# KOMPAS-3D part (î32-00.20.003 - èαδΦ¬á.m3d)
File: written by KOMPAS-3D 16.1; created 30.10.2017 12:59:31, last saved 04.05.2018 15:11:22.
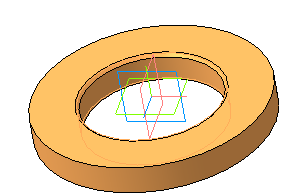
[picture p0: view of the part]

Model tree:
1. Эскиз:12
2. Операция вращения:1
     Угол 1 = 360
3. Условное изображение резьбы:1  (labels: M125x3)
     Длина резьбы = 25; Шаг резьбы = 3; Номинальный диаметр резьбы = 125
4. Подгонка:1
5. Фаска:2
     Угол = 45; Длина 1 = 1; Длина 2 = 1
6. Эскиз:14
7. Вырезать элемент выдавливания:1
     Толщина стенки 2 = 4; Расстояние 2 = 5; Расстояние 1 = 10.5; На расстояние 1 = 14.5
8. Фаска:3
     Угол = 45; Длина 1 = 3; Длина 2 = 3
9. Фаска:4
     Угол = 45; Длина 1 = 3; Длина 2 = 3
10. Эскиз:15
11. Вырезать элемент выдавливания:2
     Расстояние 1 = 5
12. Эскиз:16
13. Эскиз:13
14. Отверстие:1
     Глубина выреза = 40; Диаметр отверстия = 10.5; Угол конуса торца = 118; Координата Y = -108
15. Массив по концентрической сетке:1  (with: Отверстие:1, Эскиз:13)  (labels: Полипропилен  ГОСТ 26996-86)  (8 pattern instances)
     Геометрический массив = 7; Шаг 2 = 360

Expressions: 204.6/2
Referenced files in C:\Program Files\ASCON\KOMPAS-3D V16\Sys\Thread\: cil0_8724-2002 fine.xml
